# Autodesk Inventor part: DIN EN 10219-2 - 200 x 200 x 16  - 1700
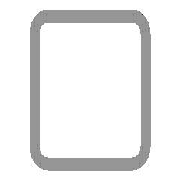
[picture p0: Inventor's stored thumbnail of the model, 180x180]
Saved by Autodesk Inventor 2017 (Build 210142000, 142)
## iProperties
Created: 2016-02
Part Number: DIN EN 10219-2 - 200 x 200 x 16  - 1700
Material: Steel, Mild
Description: Cold formed welded structural hollow sections of non-alloy and fine grain structural steel
Document SubType Name: Modeling
Standard: DIN
Designer: iusti
Standard Revision: 2006-07
Standards Organization: DIN
Language: en-US
Size Designation: 200 x 200 x 16
Categories: <MemberInstance><Categories><Category DisplayName="Structural Shapes" InternalName="089c4875-fa83-4c05-b084-43b9cc11f5ed" Mnemonic="GRDR"><CategoryParameter Dis
Stock Number: 200 x 200 x 16
Density: 7.85 g/cm^3
Appearance: Semi-Polished
Mass: 125724 g
Surface Area: 20321.8 cm^2
Volume: 16015.9 cm^3
G_L: 1700.000 mm
G_W: 200.000 mm
G_H: 200.000 mm
+B125B8ED-1570-405A-A825-64B3EFBC6DC3+CUTDETAIL1: Miter 45.00 deg
+1BFDA885-F50F-46B1-BDA8-57B8AE23BE4C+CUTDETAIL2: Miter 45.00 deg
_CCFamilyMember: 103
_CCFamilyDisplayName: DIN EN 10219-2 (Square Hollow Section - Cold Formed) - Cold formed welded structural hollow sections of non-alloy and fine grain structural steel
_FrameMemberDoc: Frame Member File
_Version: 15.0.0
_GetPNFromCC: 1
Author: iusti
IsCustomPart: 1
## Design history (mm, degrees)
node "Start plane"
node "End plane"
sketch "Sketch"
  geometry: L1 (-100, -52)-(-100, 52); L2 (-52, 100)-(52, 100); L3 (100, 52)-(100, -52); L4 (52, -100)-(-52, -100); L5 (-52, 84)-(52, 84); L6 (84, 52)-(84, -52); L7 (52, -84)-(-52, -84); L8 (-84, -52)-(-84, 52); L9 (0, 153.918)-(0, -153.918) reference; L10 (-153.918, 0)-(153.918, 0) reference; A1 r 48 centre (-52, -52) between (-100, -52) and (-52, -100); A2 r 48 centre (-52, 52) between (-52, 100) and (-100, 52); A3 r 48 centre (52, 52) between (100, 52) and (52, 100); A4 r 48 centre (52, -52) between (52, -100) and (100, -52); A5 r 32 centre (-52, 52) between (-52, 84) and (-84, 52); A6 r 32 centre (52, 52) between (84, 52) and (52, 84); A7 r 32 centre (52, -52) between (52, -84) and (84, -52); A8 r 32 centre (-52, -52) between (-84, -52) and (-52, -84)
  constraints: 16 end point, 16 point on circle, 8 centre point, 8 tangent, 4 parallel, 3 equal radius, 2 perpendicular, 7 other
  dimensions: "d7" = 48 radius of A1 (= G_IR); "d10" = 200 distance between parallel lines of L2 L4 (= G_H); "d11" = 200 distance between parallel lines of L1 L3 (= G_W); "d12" = 16 distance between parallel lines of L3 L6 (= G_T); "d15" = 100 distance between parallel lines of L2 L10 (= 0.5 x d10); "d16" = 100 distance between parallel lines of L9 L3 (= 0.5 x d11)
extrude "Body" new body sketch "Sketch" stored distance "d3" = 1700 (= G_L); taper "d4" = 0 deg
node "Driven Length"
  sketch "Sketch3"
    geometry: L1 (0, 0)-(10, 0) reference
    constraints: 2 end point, 1 horizontal
  workplane "Work Plane3"
  sketch "Sketch4"
    geometry: L1 (-2, -100)-(12, -100) reference; L2 (-2, 1600)-(12, 1600) reference
    dimensions: "d18" = 1700 distance between parallel lines of L1 L2 (derived)
workplane "Work Plane4"
split "Split1"
workplane "Work Plane5"
split "Split2"
body "Solid1"
other parameters: "G_W" = 200 [user parameter; used in 1 equation term], "G_H" = 200 [user parameter; used in 1 equation term], "G_T" = 16 [user parameter; used in 1 equation term], "G_IR" = 48 [user parameter; used in 1 equation term], "G_L" = 1700 (= d18) [user parameter; used in 1 equation term], "d17" = 90 deg
